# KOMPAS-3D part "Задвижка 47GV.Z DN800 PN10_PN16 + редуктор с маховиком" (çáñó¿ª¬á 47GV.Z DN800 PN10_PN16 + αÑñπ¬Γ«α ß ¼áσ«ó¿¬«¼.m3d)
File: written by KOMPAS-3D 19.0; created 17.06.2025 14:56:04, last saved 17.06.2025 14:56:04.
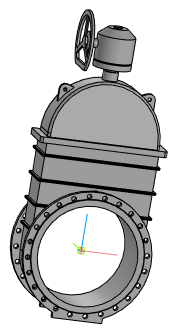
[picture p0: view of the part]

Document properties: Полное имя файла: Задвижка 47GV.Z DN800 PN10_PN16 + редуктор с маховиком.a3d

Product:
- Part/product: Задвижка 47GV.Z DN800 PN10_PN16 + редуктор с маховиком
    Масса: 2619.13

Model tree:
1. Операция без истории:1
